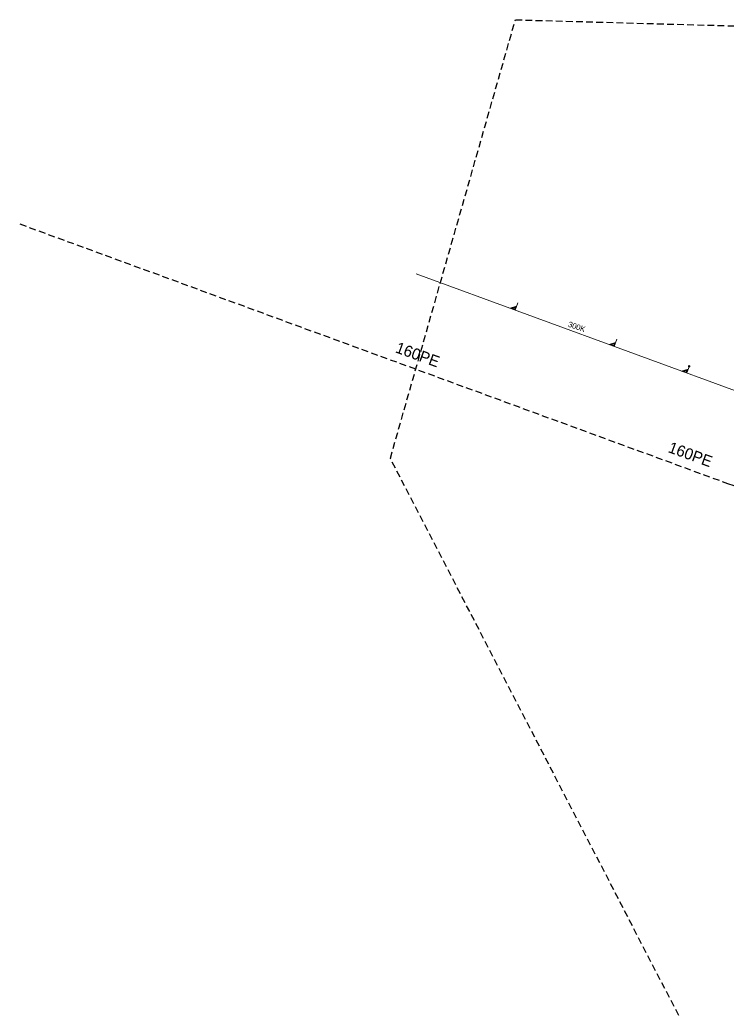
# Model space of a CAD drawing. Extents: x -735085 to -733500, y -1044153 to -1043402.
# Drawn here: x -735085.3 to -734984.7, y -1043574.9 to -1043433.9 of the extents above; entities that cross this region are included whole.
import ezdxf

# ---------------------------------------------------------------- set-up
doc = ezdxf.new("R2010")
doc.units = 0
doc.header["$LTSCALE"] = 0.32
doc.linetypes.add('MEDIUM_DASHED', pattern=[4.5, 3, -1.5])
doc.layers.add('15', color=7, linetype='Continuous')
doc.layers.add('16', color=7, linetype='Continuous')
for name, color, linetype, lineweight in [('18', 7, 'Continuous', 13), ('20', 7, 'Continuous', 13), ('63', 7, 'MEDIUM_DASHED', 25), ('8', 7, 'Continuous', 13)]:
    doc.layers.add(name, color=color, linetype=linetype, lineweight=lineweight)

msp = doc.modelspace()

# ---------------------------------------------------------------- linework, layer by layer
at = {"layer": '18'}
for points in [[(-735014.321, -1043474.244), (-735014.699, -1043475.273), (-735015.422, -1043475.008), (-735014.5, -1043474.73)], [(-735014.587, -1043474.824), (-735014.73, -1043475.214), (-735015.262, -1043475.02), (-735014.587, -1043474.823)], [(-735014.66, -1043474.887), (-735014.76, -1043475.16), (-735015.11, -1043475.032), (-735014.659, -1043474.887)], [(-735000.238, -1043479.41), (-735000.616, -1043480.439), (-735001.339, -1043480.174), (-735000.417, -1043479.896)], [(-735000.504, -1043479.99), (-735000.647, -1043480.38), (-735001.179, -1043480.186), (-735000.504, -1043479.989)], [(-735000.577, -1043480.053), (-735000.677, -1043480.326), (-735001.027, -1043480.198), (-735000.576, -1043480.053)], [(-734989.909, -1043483.196), (-734990.286, -1043484.224), (-734991.009, -1043483.958), (-734990.087, -1043483.681)], [(-734990.175, -1043483.775), (-734990.318, -1043484.165), (-734990.849, -1043483.97), (-734990.174, -1043483.774)], [(-734990.248, -1043483.837), (-734990.348, -1043484.111), (-734990.697, -1043483.983), (-734990.247, -1043483.838)]]:
    msp.add_lwpolyline(points, dxfattribs=at)
for points in [[(-734990.03, -1043483.251), (-734990.035, -1043483.285), (-734990.029, -1043483.318), (-734990.012, -1043483.346), (-734989.985, -1043483.367), (-734989.954, -1043483.377), (-734989.921, -1043483.376), (-734989.889, -1043483.363), (-734989.865, -1043483.34), (-734989.851, -1043483.31), (-734989.847, -1043483.277), (-734989.855, -1043483.244), (-734989.875, -1043483.217), (-734989.902, -1043483.198), (-734989.935, -1043483.189), (-734989.969, -1043483.193), (-734989.998, -1043483.209), (-734990.021, -1043483.233)], [(-734990.004, -1043483.262), (-734990.009, -1043483.29), (-734990.001, -1043483.317), (-734989.982, -1043483.338), (-734989.957, -1043483.35), (-734989.929, -1043483.351), (-734989.903, -1043483.339), (-734989.884, -1043483.319), (-734989.875, -1043483.292), (-734989.878, -1043483.265), (-734989.892, -1043483.24), (-734989.915, -1043483.223), (-734989.942, -1043483.217), (-734989.97, -1043483.224), (-734989.992, -1043483.241)]]:
    msp.add_lwpolyline(points, close=True, dxfattribs=at)
at = {"layer": '20'}
msp.add_lwpolyline([(-734936.44, -1043504.38), (-734981.37, -1043487.5), (-735028.8, -1043470.1)], dxfattribs=at)
msp.add_lwpolyline([(-734936.44, -1043504.38), (-734981.37, -1043487.5), (-735028.8, -1043470.1)], dxfattribs=at)
at = {"layer": '63'}
msp.add_lwpolyline([(-734796.022, -1043808.279), (-734957.658, -1043641.023), (-734957.66, -1043641.021), (-735032.487, -1043496.398), (-735032.488, -1043496.396), (-735032.488, -1043496.394), (-735032.488, -1043496.393), (-735032.488, -1043496.391), (-735014.686, -1043433.916), (-735014.686, -1043433.914), (-735014.685, -1043433.913), (-735014.683, -1043433.911), (-735014.682, -1043433.91), (-735014.68, -1043433.909), (-735014.678, -1043433.909), (-735014.676, -1043433.909), (-734957.569, -1043435.5), (-734957.567, -1043435.5), (-734957.565, -1043435.501), (-734250.468, -1043761.931)], dxfattribs=at)
at = {"layer": '8', "linetype": 'MEDIUM_DASHED', "lineweight": 25}
msp.add_lwpolyline([(-735085.256, -1043462.997), (-734984.456, -1043499.972), (-734967.581, -1043505.873)], dxfattribs=at)

# ---------------------------------------------------------------- texts
at = {"layer": '15'}
for p in [(-735031.881, -1043481.265), (-734993.042, -1043495.487)]:
    msp.add_text('160PE ', height=1.6, rotation=340, dxfattribs=at).set_placement(p)
at = {"layer": '16'}
msp.add_text('300K', height=0.8, rotation=341, dxfattribs=at).set_placement((-735007.242, -1043477.618))

doc.saveas('drawing.dxf')
